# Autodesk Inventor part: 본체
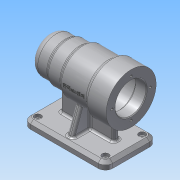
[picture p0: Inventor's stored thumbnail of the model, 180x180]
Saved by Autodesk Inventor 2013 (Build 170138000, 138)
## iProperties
Created: 2016-06
Part Number: 본체
Material: 알루미늄 6061
Document SubType Name: Modeling
Designer: Administrator
Density: 2.71 g/cm^3
Mass: 673.894 g
Surface Area: 647.184 cm^2
Volume: 248.669 cm^3
Author: Administrator
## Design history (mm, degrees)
sketch "스케치1"
  geometry: L1 (-56, 0)-(56, 0); L2 (56, 34)-(28, 34); L3 (28, 34)-(28, 30); L4 (28, 30)-(-11, 30); L5 (-11, 30)-(-11, 27); L6 (-11, 27)-(-31, 27); L7 (-31, 27)-(-31, 25); L8 (-31, 25)-(-56, 25); L9 (-56, 25)-(-56, 0); L10 (56, 34)-(56, 21); L11 (56, 21)-(41, 21); L12 (41, 21)-(41, 24); L13 (41, 24)-(-13, 24); L14 (-13, 24)-(-13, 21); L15 (-13, 21)-(-25, 21); L16 (-25, 21)-(-25, 17.5); L17 (-25, 17.5)-(-43, 17.5); L18 (-43, 17.5)-(-43, 16); L19 (-43, 16)-(-47, 16); L20 (-47, 16)-(-47, 10.5); L21 (-47, 10.5)-(-50, 10.5); L22 (-50, 10.5)-(-50, 0); 2 further points
  constraints: 44 end point, 13 parallel, 3 perpendicular, 1 coincident, 1 collinear, 1 horizontal, 1 midpoint, 1 point on line, 1 vertical alignment
  dimensions: "d0" = 112 distance of L1.start L1.end; "d2" = 50 diameter of L8 L1; "d3" = 54 diameter of L6 L1; "d4" = 60 diameter of L4 L1; "d5" = 68 diameter of L2 L1; "d6" = 84 distance between parallel lines of L9 L3; "d7" = 45 distance between parallel lines of L9 L5; "d8" = 25 distance of L7.end L8.end; "d9" = 42 diameter of L11 L1; "d10" = 48 diameter of L13 L1; "d11" = 42 diameter of L15 L1; "d12" = 35 diameter of L17 L1; "d13" = 32 diameter of L19 L1; "d14" = 21 diameter of L21 L1; "d15" = 15 distance between parallel lines of L10 L12; "d16" = 54 distance between parallel lines of L14 L12; "d17" = 12 distance of L14.end L15.end; "d18" = 18 distance of L16.end L17.end; "d19" = 4 distance of L18.end L19.end; "d20" = 3 distance of L20.end L21.end
revolve "회전1" sketch "스케치1" stored, may be unused: angle "d21" = 90 deg
fillet "모깎기1" dims "d22" = 3
node "작업 평면1"
sketch "스케치2"
  geometry: L1 (56, -35)-(-56, -35); L2 (-56, -35)-(-56, 35); L3 (-56, 35)-(56, 35); L4 (56, 35)-(56, -35); 1 further point
  constraints: 8 end point, 2 parallel, 1 horizontal, 1 perpendicular
  dimensions: "d24" = 112 distance of L1.start L1.end; "d26" = 70 distance of L1.end L2.end; "d27" = 35 distance from line of point (0, 0) L1; "d28" = 56 distance from line of point (0, 0) L2
extrude "돌출1" join sketch "스케치2" distance "d29" = 10; taper "d30" = 0 deg
fillet "모깎기2" dims "d31" = 10
fillet "모깎기3" dims "d32" = 10
chamfer "모따기1" distance "d33" = 4; stored, may be unused: second distance "d34" = 2, angle "d35" = 45 deg
sketch "스케치3"
  geometry: L1 (-36, 4)-(-36, -4); L2 (-36, -4)-(36, -4); L3 (36, -4)-(36, 4); L4 (36, 4)-(-36, 4); L5 (-56, 25)-(-56, -25) reference; L6 (56, -25)-(56, 25) reference; 2 further points
  constraints: 8 end point, 1 horizontal, 1 horizontal alignment, 1 midpoint, 1 parallel
  dimensions: "d39" = 8 distance between parallel lines of L2 L4; "d41" = 20 distance between parallel lines of L5 L1; "d42" = 20 distance between parallel lines of L6 L3
extrude "돌출2" join sketch "스케치3" stored distance "d43" = 10; taper "d44" = 0 deg
node "작업 평면2"
sketch "스케치4"
  geometry: L1 (-3, 10)-(6.127, 35.077); L2 (53, 10)-(43.844, 35.157); L3 (-10, 0)-(-10, 6) reference; L4 (60, 6)-(60, 0) reference; L5 (-6, 10)-(0, 10) reference; L6 (50, 10)-(56, 10) reference; 1 further point
  constraints: 4 end point, 2 midpoint
  dimensions: "d46" = 7 distance from line of L3 L1.start; "d47" = 7 distance from line of L4 L2.start; "d48" = 110 deg angle of L6 L2; "d49" = 110 deg angle of L5 L1
feature "리브1" dims "d50" = 1, "d51" = 8, "d52" = 0, "d53" = 0, "d54" = 1, "d55" = 1
feature "리브2" dims "d56" = 1, "d57" = 8, "d58" = 0, "d59" = 0, "d60" = 1, "d61" = 1
hole "구멍1" diameter "d64" = 5; stored, may be unused: countersink angle "d68" = 90 deg, drill point angle "d70" = 118 deg; dims "d62" = 10, "d63" = 10, "d65" = 6, "d66" = 9, "d67" = 4, "d69" = 8
hole "구멍2" diameter "d73" = 5; stored, may be unused: countersink angle "d77" = 90 deg, drill point angle "d79" = 118 deg; dims "d71" = 10, "d72" = 10, "d74" = 6, "d75" = 9, "d76" = 4, "d78" = 8
hole "구멍3" diameter "d82" = 5; stored, may be unused: countersink angle "d86" = 90 deg, drill point angle "d88" = 118 deg; dims "d80" = 10, "d81" = 10, "d83" = 6, "d84" = 9, "d85" = 4, "d87" = 8
hole "구멍4" diameter "d91" = 5; stored, may be unused: countersink angle "d95" = 90 deg, drill point angle "d97" = 118 deg; dims "d89" = 10, "d90" = 10, "d92" = 6, "d93" = 9, "d94" = 4, "d96" = 8
fillet "모깎기4" dims "d98" = 3
fillet "모깎기5" dims "d99" = 3
fillet "모깎기6" dims "d100" = 3
fillet "모깎기7" dims "d101" = 10
fillet "모깎기8" dims "d102" = 0.3
fillet "모깎기9" dims "d103" = 3
fillet "모깎기10" dims "d108" = 3
chamfer "모따기2" distance "d109" = 1; stored, may be unused: second distance "d110" = 2, angle "d111" = 45 deg
sketch "스케치5"
  geometry: 2 further points
  constraints: 1 vertical alignment
  dimensions: "d112" = 26 distance of point (0, 0) point (0, 26)
hole "구멍5" sketch "스케치5" at (0, 26) diameter "d113" = 3.242; stored, may be unused: countersink angle "d117" = 90 deg, drill point angle "d119" = 118 deg; dims "d114" = 8, "d115" = 9, "d116" = 4, "d118" = 11
fillet "모깎기11" dims "d123" = 3
fillet "모깎기12" dims "d124" = 3
node "작업 평면3"
sketch "스케치6"
  geometry: L1 (-64.5, -15)-(-64.5, 15) reference; L2 (47.5, -22)-(47.5, 22) reference; 2 further points
  constraints: 1 horizontal alignment, 1 midpoint, 1 other
  dimensions: "d125" = 48 distance from line of L2 point (-0.5, 0)
feature "엠보싱1" sketch "스케치6" dims "d0" = 112, "d2" = 50, "d3" = 54, "d4" = 60, "d5" = 68, "d6" = 84, "d7" = 45, "d8" = 25, "d9" = 42, "d10" = 48, "d11" = 42, "d12" = 35, "d13" = 32, "d14" = 21, "d15" = 15, "d16" = 54, "d17" = 12, "d18" = 18, "d19" = 4, "d20" = 3, "d126" = 0.5, "d127" = 0
node "솔리드1"
pattern_circular "원형 패턴1" dims angle "d121" = 360 deg
other parameters: "d45" = -56
